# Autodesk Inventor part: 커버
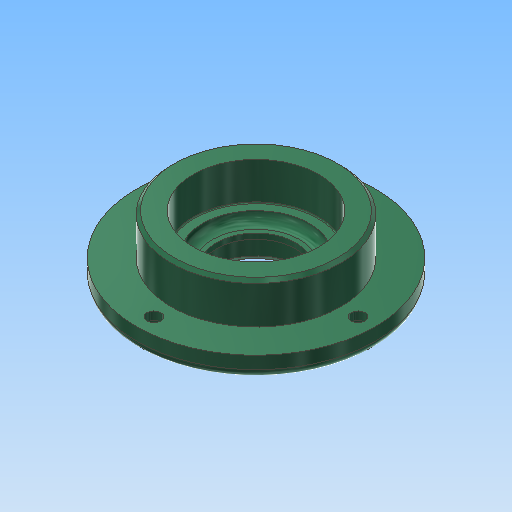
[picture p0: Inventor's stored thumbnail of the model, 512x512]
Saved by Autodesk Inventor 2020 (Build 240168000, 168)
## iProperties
Created: 2016-04
Part Number: 커버
Document SubType Name: Modeling
Designer: mdu
Density: 7.86 g/cm^3
Mass: 351.567 g
Surface Area: 161.165 cm^2
Volume: 44.7286 cm^3
Material: 강철, 연강
Appearance: 강철
Company: 한국ATC센터
Author: mdu
Revision Number: 1
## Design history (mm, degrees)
sketch "스케치1"
  geometry: C1 r 38 at (0, 0); 1 further point
  constraints: 1 centre point, 1 coincident
  dimensions: "d0" = 76 diameter of C1
extrude "돌출1" new body sketch "스케치1" distance "d1" = 7; taper "d2" = 0 deg
sketch "스케치2"
  geometry: C1 r 27 at (0, 0); 1 further point
  constraints: 1 centre point, 1 coincident
  dimensions: "d3" = 54 diameter of C1
extrude "돌출2" join sketch "스케치2" distance "d4" = 13; taper "d5" = 0 deg
sketch "스케치3"
  geometry: C1 r 20 at (0, 0); 1 further point
  constraints: 1 centre point, 1 coincident
  dimensions: "d6" = 40 diameter of C1
extrude "돌출3" join sketch "스케치3" distance "d7" = 5; taper "d8" = 0 deg
hole "구멍1" diameter "d11" = 25; stored, may be unused: countersink angle "d15" = 90 deg, drill point angle "d17" = 118 deg; dims "d9" = 10, "d10" = 10, "d12" = 6, "d13" = 32, "d14" = 8.3, "d16" = 8
hole "구멍2" diameter "d20" = 34; stored, may be unused: countersink angle "d24" = 90 deg, drill point angle "d26" = 0 deg; dims "d18" = 10, "d19" = 10, "d21" = 6, "d22" = 40, "d23" = 12, "d25" = 3
fillet "모깎기2" dims "d34" = 3
fillet "모깎기1" dims "d27" = 0.3
chamfer "모따기1" distance "d28" = 1; stored, may be unused: second distance "d29" = 2, angle "d30" = 45 deg
chamfer "모따기2" distance "d31" = 1.2; stored, may be unused: second distance "d32" = 2, angle "d33" = 30 deg
sketch "스케치4" dims "d35" = 65
  geometry: 3 further points
  constraints: 2 horizontal alignment, 1 coincident, 2 other
hole "구멍3" sketch "스케치4" at (32.5, 0) diameter "d36" = 4.5; stored, may be unused: countersink angle "d40" = 90 deg, drill point angle "d42" = 118 deg; dims "d37" = 6, "d38" = 8, "d39" = 4.4, "d41" = 13
node "솔리드1"
pattern_circular "원형 패턴1" dims angle "d44" = 360 deg
